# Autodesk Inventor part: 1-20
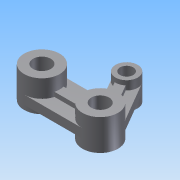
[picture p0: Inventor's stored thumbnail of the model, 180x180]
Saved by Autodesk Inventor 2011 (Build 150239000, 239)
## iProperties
Created: 2014-02
Part Number: 1-20
Document SubType Name: Modeling
Designer: Administrator
Density: 1 g/cm^3
Author: Administrator
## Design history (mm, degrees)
sketch "草图1"
  geometry: L1 (-26.261, 8)-(-10.471, 8); L2 (-26.261, -8)-(0, -8); L3 (-4.006, 22.727)-(6.909, 4.034); L4 (-12.641, 17.685)-(-8.743, 11.008); A1 r 8 centre (0, 0) between (0, -8) and (6.909, 4.034); A2 r 8 centre (-26.261, 0) between (-26.261, 8) and (-26.261, -8); A3 r 5 centre (-8.324, 20.206) between (-4.006, 22.727) and (-12.641, 17.685); A4 r 2 centre (-10.471, 10) between (-10.471, 8) and (-8.743, 11.008); 1 further point
  constraints: 8 end point, 8 point on circle, 8 tangent, 4 centre point, 1 coincident
  dimensions: "d0" = 16 diameter of A1; "d1" = 16 diameter of A2; "d2" = 10 diameter of A3; "d3" = 2 radius of A4
extrude "拉伸1" new body sketch "草图1" distance "d4" = 4; taper "d5" = 0 deg
sketch "草图3"
  geometry: A1 r 8 centre (26.261, 0) between (26.261, -8) and (26.261, 8) reference; A2 r 8 centre (0, 0) between (-6.909, 4.034) and (0, -8) reference; 2 further points
  constraints: 2 coincident, 2 vertical alignment, 4 other
extrude "拉伸3" join sketch "草图3" distance "d8" = 4; taper "d9" = 0 deg
sketch "草图4"
  geometry: C1 r 5 at (8.324, 20.206); A1 r 5 centre (8.324, 20.206) between (12.641, 17.685) and (4.006, 22.727) reference
  constraints: 1 centre point, 1 coincident, 1 concentric
extrude "拉伸4" join sketch "草图4" distance "d10" = 4; taper "d11" = 0 deg
sketch "草图5"
  geometry: C1 r 8 at (0, 0); C2 r 8 at (-26.261, 0); A1 r 8 centre (-26.261, 0) between (-26.261, 8) and (-26.261, -8) reference; A2 r 8 centre (0, 0) between (0, -8) and (6.909, 4.034) reference
  constraints: 2 centre point, 2 coincident, 2 concentric
extrude "拉伸5" join sketch "草图5" distance "d12" = 6; taper "d13" = 0 deg
sketch "草图6"
  geometry: C1 r 5 at (-8.324, 20.206); A1 r 5 centre (-8.324, 20.206) between (-4.006, 22.727) and (-12.641, 17.685) reference
  constraints: 1 centre point, 1 coincident, 1 concentric
extrude "拉伸6" join sketch "草图6" distance "d14" = 4; taper "d15" = 0 deg
sketch "草图7"
  geometry: L1 (0, -8)-(-26.261, -8) reference; L2 (-4.006, 22.727)-(6.909, 4.034) reference; L3 (-7.74, 2.024)-(-18.522, 2.024); L4 (-7.727, -2.071)-(-18.534, -2.071); L5 (-0.068, 8)-(-5.009, 16.462); L6 (-8.736, 15.223)-(-3.845, 7.015); A1 r 5 centre (-8.324, 20.206) between (-12.641, 17.685) and (-4.006, 22.727) reference; A2 r 8 centre (-26.261, 0) between (-26.261, -8) and (-26.261, 8) reference; A3 r 8 centre (0, 0) between (6.909, 4.034) and (0, -8) reference; A4 r 8 centre (0, 0) between (0, -8) and (6.909, 4.034) reference
  constraints: 12 point on circle, 8 end point, 3 parallel
extrude "拉伸7" join sketch "草图7" distance "d16" = 2; taper "d17" = 0 deg
sketch "草图8"
  geometry: L1 (7.727, -2.071)-(18.534, -2.071) reference; L2 (18.522, 2.024)-(7.74, 2.024) reference; L3 (3.845, 7.015)-(8.736, 15.223) reference; L4 (5.009, 16.462)-(0.068, 8) reference; A1 r 8 centre (0, 0) between (7.727, -2.071) and (7.74, 2.024) reference; A2 r 5 centre (8.324, 20.206) between (8.736, 15.223) and (5.009, 16.462) reference; A3 r 8 centre (26.261, 0) between (18.534, -2.071) and (18.522, 2.024) reference
extrude "拉伸8" join sketch "草图8" distance "d18" = 2; taper "d19" = 0 deg
hole "Hole1" diameter "d22" = 8; stored, may be unused: countersink angle "d26" = 90 deg, drill point angle "d28" = 0 deg; dims "d20" = 10, "d21" = 10, "d23" = 6, "d24" = 4, "d25" = 2, "d27" = 8
hole "Hole2" diameter "d31" = 8; stored, may be unused: countersink angle "d35" = 90 deg, drill point angle "d37" = 0 deg; dims "d29" = 10, "d30" = 10, "d32" = 6, "d33" = 4, "d34" = 2, "d36" = 8
hole "Hole3" diameter "d40" = 6; stored, may be unused: countersink angle "d44" = 90 deg, drill point angle "d46" = 118 deg; dims "d38" = 10, "d39" = 10, "d41" = 6, "d42" = 4, "d43" = 2, "d45" = 8
sketch "草图9"
  geometry: C1 r 4 at (0, 0) reference; C2 r 8 at (0, 0) reference; 1 further point
extrude "拉伸9" cut sketch "草图9" distance "d47" = 2; taper "d48" = 0 deg
sketch "草图10"
  geometry: C1 r 4 at (0, 0) reference; C2 r 8 at (0, 0) reference; 1 further point
extrude "拉伸10" join sketch "草图10" distance "d49" = 2; taper "d50" = 0 deg
node "实体1"
